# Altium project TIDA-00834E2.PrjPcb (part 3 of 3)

## Sheet TIDA-00834E2_Pg10_EVM_Hardware.SchDoc: EVM_Hardware
size 431 x 279 mm; Date: Not shown in title block; ApprovedBy: Not shown in title block; CheckedBy: Not shown in title block; Author: Not shown in title block; CompanyName: Not shown in title block; DrawnBy: Sreenivasa; Engineer: Not shown in title block; Organization: Not shown in title block; Address1: Not shown in title block; Address2: Not shown in title block; Address3: Not shown in title block; Address4: Not shown in title block; DocumentNumber: 1; Revision: Use project parameter SCH_Rev; SheetNumber: 10; SheetTotal: 10; PageSetup: Record=PageOptions¦CenterHorizontal=True¦CenterVertical=True¦PrintScale=1.00¦XCorrection=1.00¦YCorrection=1.00¦PrintKind=0¦BorderSize=5000000¦LeftOffset=0¦BottomOffset=0¦Orientation=2¦PaperLength=1000¦PaperWidth=1000¦Scale=100¦PaperSource=15¦PrintQuality=600¦MediaType=1¦DitherType=10¦PaperKind=Letter¦PrintScaleMode=1
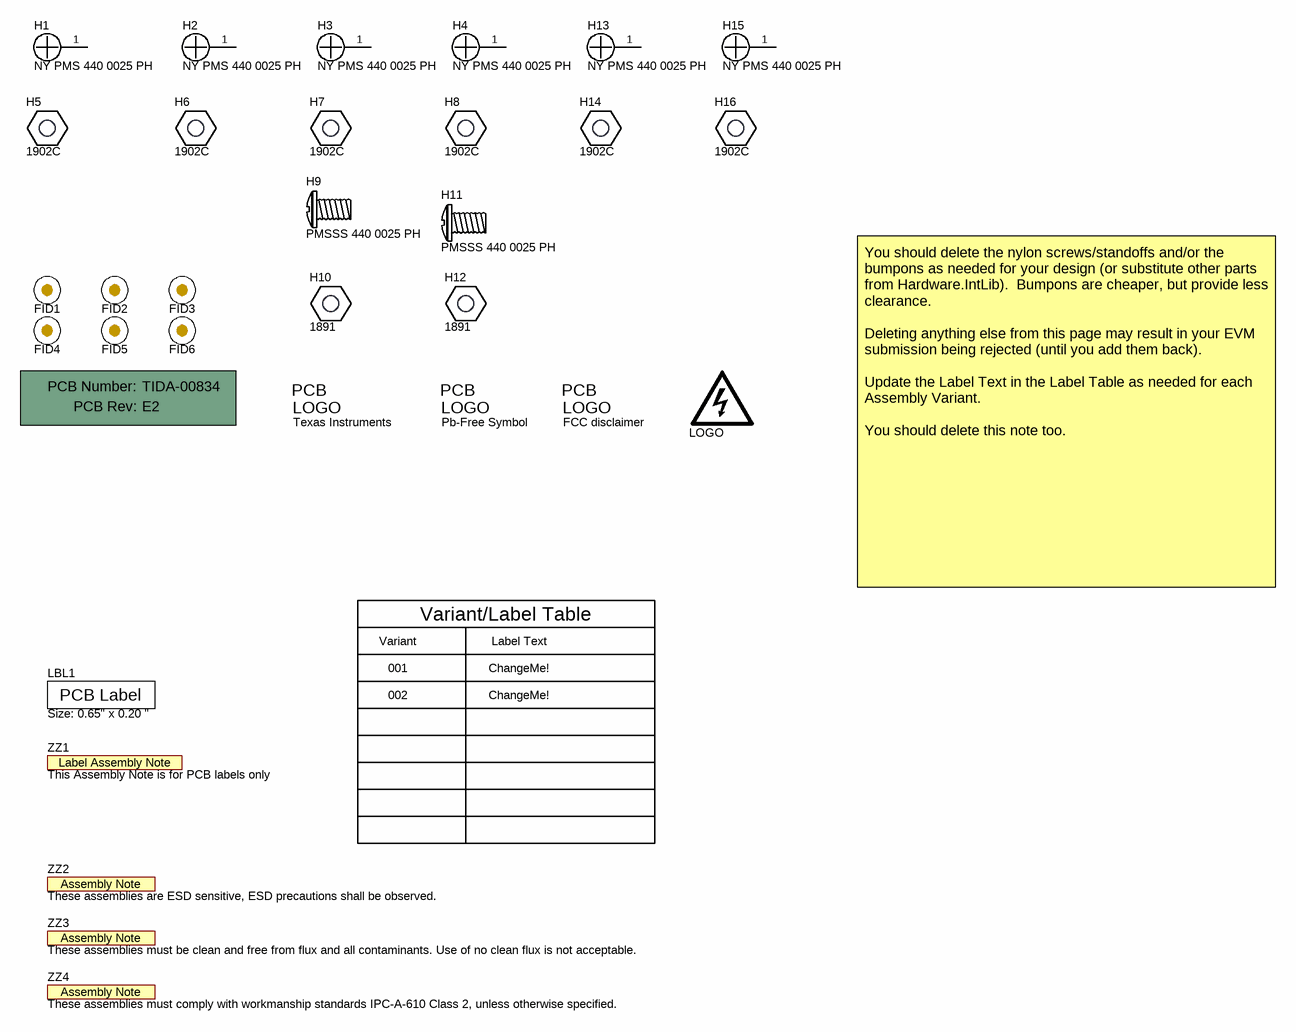
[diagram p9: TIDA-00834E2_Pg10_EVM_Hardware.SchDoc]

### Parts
!PCB1  Printed Circuit Board  (value not drawn)  (mechanical)
FID1  Fiducial  [Fiducial10-20]  (value not drawn)
FID2  Fiducial  [Fiducial10-20]  (value not drawn)
FID3  Fiducial  [Fiducial10-20]  (value not drawn)
FID4  Fiducial  [Fiducial10-20]  (value not drawn)
FID5  Fiducial  [Fiducial10-20]  (value not drawn)
FID6  Fiducial  [Fiducial10-20]  (value not drawn)
H1  NY PMS 440 0025 PH  [NY PMS 440 0025 PH]
H2  NY PMS 440 0025 PH  [NY PMS 440 0025 PH]
H3  NY PMS 440 0025 PH  [NY PMS 440 0025 PH]
H4  NY PMS 440 0025 PH  [NY PMS 440 0025 PH]
H5  1902C  [Keystone_1902C]
H6  1902C  [Keystone_1902C]
H7  1902C  [Keystone_1902C]
H8  1902C  [Keystone_1902C]
H9  PMSSS 440 0025 PH  [B_F_PMSSS4400025PH]
H10  1891  [Keystone_1891]
H11  PMSSS 440 0025 PH  [B_F_PMSSS4400025PH]
H12  1891  [Keystone_1891]
H13  NY PMS 440 0025 PH  [NY PMS 440 0025 PH]
H14  1902C  [Keystone_1902C]
H15  NY PMS 440 0025 PH  [NY PMS 440 0025 PH]
H16  1902C  [Keystone_1902C]
LBL1  Size: 0.65" x 0.20 "  [Label_650x200]
LOGO  DANGER HIGH VOLTAGE  [IEC_HighVoltage_Large]  (value not drawn)  (no BOM)
Logo1  Texas Instruments  [TI_Stacked_Overlay_Small]  (no BOM)
Logo2  Pb-Free Symbol  [Pb-Free_Overlay_Small]  (no BOM)
Logo3  FCC disclaimer  [FCC_disclaimer]  (no BOM)
ZZ1  This Assembly Note is for PCB labels only  [AssemblyNoteLabel]  (no BOM)
ZZ2  These assemblies are ESD sensitive, ESD precautions shall be observed.  [AssemblyNote]  (no BOM)
ZZ3  These assemblies must be clean and free from flux and all contaminants. Use of no clean flux is not acceptable.  [AssemblyNote]  (no BOM)
ZZ4  These assemblies must comply with workmanship standards IPC-A-610 Class 2, unless otherwise specified.  [AssemblyNote]  (no BOM)

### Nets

Not connected (* = marked no-connect by the designer): H1 1; H2 1; H3 1; H4 1; H13 1; H15 1

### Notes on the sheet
- Variant
- Variant/Label Table
- Label Text
- You should delete the nylon screws/standoffs and/or the bumpons as needed for your design (or substitute other parts from Hardware.IntLib).  Bumpons are cheaper, but provide less clearance.
  Deleting anything else from this page may result in your EVM submission being rejected (until you add them back).
  Update the Label Text in the Label Table as needed for each Assembly Variant.
  You should delete this note too.
- 001
- 002
- ChangeMe!

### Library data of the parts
!PCB1 = PCB: Manufacturer: Any; PartNumber: TIDA-00834; SymbolCreator: a0412235
FID1-FID6 = Fiducial: Fiducial mark.  There is nothing to buy or mount.; SymbolCreator: codlsc
H1-H4 H13 H15 = NY PMS 440 0025 PH: Machine Screw, Round, #4-40 x 1/4, Nylon, Philips panhead; Manufacturer: B&F Fastener Supply; CompType: Hardware; SymbolCreator: codlsc; U/M: EA
H5-H8 H14 H16 = 1902C: Standoff, Hex, 0.5"L #4-40 Nylon; Manufacturer: Keystone; CompType: Hardware
H9 H11 = PMSSS 440 0025 PH: MACHINE SCREW PAN PHILLIPS 4-40; Manufacturer: B&F Fastener Supply; SymbolCreator: a0412235; CompType: Standoff
H10 H12 = 1891: Hex Standoff, #4-40, Aluminum, 1/4"; Manufacturer: Keystone; SymbolCreator: a0412235
LBL1 = THT-14-423-10: Thermal Transfer Printable Labels, 0.650" W x 0.200" H - 10,000 per roll; Manufacturer: Brady; SymbolCreator: a0412235; CompType: Label
LOGO = IEC_HighVoltage: IEC 61010-1 High Voltage Warning; SymbolCreator: a0412235
Logo1 = TI_Logo: Texas Instrument Corporate Signature; SymbolCreator: codlsc
Logo2 = Pb-Free: SymbolCreator: a0412235
Logo3 = FCC_disclaimer: SymbolCreator: codlsc
ZZ1 = AssemblyNoteLabel: SymbolCreator: a0412235
ZZ2-ZZ4 = AssemblyNote: SymbolCreator: codlsc

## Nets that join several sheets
+3.3V: TIDA-00834E2_Pg5_VOLTAGE (R25.2 R31.2), TIDA-00834E2_Pg6_VOLTAGE2 (R162.2 R168.2), TIDA-00834E2_Pg8_LDO (10 pins)
+12V: TIDA-00834E2_Pg3_CT1_CT2 (8 pins), TIDA-00834E2_Pg4_CT3_CT4 (8 pins), TIDA-00834E2_Pg5_VOLTAGE (6 pins), TIDA-00834E2_Pg6_VOLTAGE2 (6 pins), TIDA-00834E2_Pg8_LDO (12 pins)
+14V: TIDA-00834E2_Pg7_Split Rail Converter (J11.1 J15.1), TIDA-00834E2_Pg8_LDO (C57.1 C58.1 D24.1 U8.3)
-12V: TIDA-00834E2_Pg3_CT1_CT2 (8 pins), TIDA-00834E2_Pg4_CT3_CT4 (8 pins), TIDA-00834E2_Pg5_VOLTAGE (C6.2 U1.4), TIDA-00834E2_Pg6_VOLTAGE2 (C106.2 U17.4), TIDA-00834E2_Pg8_LDO (5 pins)
-14V: TIDA-00834E2_Pg7_Split Rail Converter (J12.1 J16.1), TIDA-00834E2_Pg8_LDO (C67.2 C69.1 U12.5 U12.8)
AGND: TIDA-00834E2_Pg3_CT1_CT2 (26 pins), TIDA-00834E2_Pg4_CT3_CT4 (26 pins), TIDA-00834E2_Pg5_VOLTAGE (18 pins), TIDA-00834E2_Pg6_VOLTAGE2 (18 pins), TIDA-00834E2_Pg7_Split Rail Converter (R70.1), TIDA-00834E2_Pg8_LDO (56 pins), TIDA-00834E2_Pg9_Filters (43 pins)
VBIAS: TIDA-00834E2_Pg3_CT1_CT2 (R47.1 R101.1 U3.5 U13.5), TIDA-00834E2_Pg5_VOLTAGE (R14.1 R17.1), TIDA-00834E2_Pg8_LDO (J13.2)
VBIASB: TIDA-00834E2_Pg4_CT3_CT4 (R120.1 R136.1 U6.5 U15.5), TIDA-00834E2_Pg6_VOLTAGE2 (R151.1 R154.1), TIDA-00834E2_Pg8_LDO (J47.2)
CT1_IN_+: TIDA-00834E2_Pg3_CT1_CT2 (J19.2 R35.2), TIDA-00834E2_Pg9_Filters (J20.3)
CT1_IN_-: TIDA-00834E2_Pg3_CT1_CT2 (7 pins), TIDA-00834E2_Pg9_Filters (J22.3)
CT2_IN_+: TIDA-00834E2_Pg3_CT1_CT2 (J26.2 R89.2), TIDA-00834E2_Pg9_Filters (J21.3)
CT2_IN_-: TIDA-00834E2_Pg3_CT1_CT2 (7 pins), TIDA-00834E2_Pg9_Filters (J23.3)
CT3_IN_+: TIDA-00834E2_Pg4_CT3_CT4 (J27.2 R106.2), TIDA-00834E2_Pg9_Filters (J37.3)
CT3_IN_-: TIDA-00834E2_Pg4_CT3_CT4 (7 pins), TIDA-00834E2_Pg9_Filters (J41.3)
CT4_IN_+: TIDA-00834E2_Pg4_CT3_CT4 (J29.2 R122.2), TIDA-00834E2_Pg9_Filters (J38.3)
CT4_IN_-: TIDA-00834E2_Pg4_CT3_CT4 (7 pins), TIDA-00834E2_Pg9_Filters (J42.3)
CT_1_OUT: TIDA-00834E2_Pg3_CT1_CT2 (C20.1 R45.2), TIDA-00834E2_Pg9_Filters (J6.3)
CT_2_OUT: TIDA-00834E2_Pg3_CT1_CT2 (C84.1 R99.2), TIDA-00834E2_Pg9_Filters (J7.3)
CT_3_OUT: TIDA-00834E2_Pg4_CT3_CT4 (C90.1 R118.2), TIDA-00834E2_Pg9_Filters (J39.3)
CT_4_OUT: TIDA-00834E2_Pg4_CT3_CT4 (C100.1 R134.2), TIDA-00834E2_Pg9_Filters (J40.3)
PD1_IN_+: TIDA-00834E2_Pg5_VOLTAGE (R198.1), TIDA-00834E2_Pg9_Filters (J24.3)
PD2_IN_+: TIDA-00834E2_Pg5_VOLTAGE (R199.1), TIDA-00834E2_Pg9_Filters (J25.3)
PD3_IN_+: TIDA-00834E2_Pg6_VOLTAGE2 (R202.1), TIDA-00834E2_Pg9_Filters (J43.3)
PD4_IN_+: TIDA-00834E2_Pg6_VOLTAGE2 (R203.1), TIDA-00834E2_Pg9_Filters (J44.3)
PD_OUT1: TIDA-00834E2_Pg5_VOLTAGE (C4.1 R8.2), TIDA-00834E2_Pg9_Filters (J8.3)
PD_OUT2: TIDA-00834E2_Pg5_VOLTAGE (C5.1 R10.2), TIDA-00834E2_Pg9_Filters (J9.3)
PD_OUT3: TIDA-00834E2_Pg6_VOLTAGE2 (C104.1 R145.2), TIDA-00834E2_Pg9_Filters (J45.3)
PD_OUT4: TIDA-00834E2_Pg6_VOLTAGE2 (C105.1 R147.2), TIDA-00834E2_Pg9_Filters (J46.3)

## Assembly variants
001: not fitted FID1 FID2 FID3 R14 R17 R24 R30 R42 R47 R72 R96 R101 R116 R120 R132 R136 R151 R154 R161 R167 R189 R193 R194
